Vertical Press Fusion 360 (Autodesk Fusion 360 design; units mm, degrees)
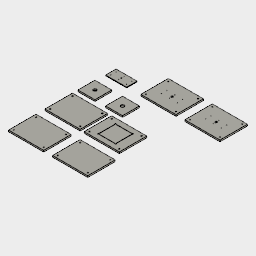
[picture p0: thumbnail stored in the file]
sketch "Top Metal"
  line L1 (240, 0) -> (0, 0)
  line L2 (240, 120) -> (240, 0)
  line L3 (0, 120) -> (240, 120)
  line L4 (0, 0) -> (0, 120)
  circle C1 centre (30, 90) radius 3.05
  circle C2 centre (30, 30) radius 3.05
  circle C3 centre (120, 90) radius 3.05
  circle C4 centre (120, 30) radius 3.05
  circle C5 centre (210, 30) radius 3.05
  circle C6 centre (210, 90) radius 3.05
  circle C7 centre (120, 60) radius 6
  point P2 (0, 0)
  point P3 (240, 0)
  point P5 (0, 120)
  point P6 (30, 90)
  point P8 (120, 90)
  point P11 (210, 90)
  point P10 (210, 30)
  point P9 (120, 30)
  point P7 (30, 30)
  point P12 (120, 60)
  dimension "d10" distance P2 P3 = 240
  dimension "d11" distance P2 P5 = 120
  dimension "d12" diameter C1 = 6.1
  dimension "d13" diameter C2 = 6.1
  dimension "d14" diameter C3 = 6.1
  dimension "d15" diameter C4 = 6.1
  dimension "d16" diameter C5 = 6.1
  dimension "d17" diameter C6 = 6.1
  dimension "d18" diameter C7 = 12
  dimension "d19" distance L4 P6 = 30
  dimension "d20" distance L4 P8 = 120
  dimension "d21" distance L2 P11 = 30
  dimension "d22" distance L2 P10 = 30
  dimension "d23" distance L4 P9 = 120
  dimension "d24" distance L4 P7 = 30
  dimension "d25" distance L4 P12 = 120
  dimension "d26" distance L3 P6 = 30
  dimension "d27" distance L3 P8 = 30
  dimension "d28" distance L3 P11 = 30
  dimension "d29" distance L1 P10 = 30
  dimension "d30" distance L1 P9 = 30
  dimension "d31" distance L1 P7 = 30
  dimension "d32" distance L1 P12 = 60
sketch "Sketch1"
  line L1 (800, 0) -> (400, 0)
  line L2 (800, 313) -> (800, 0)
  line L3 (400, 313) -> (800, 313)
  line L4 (400, 0) -> (400, 313)
  line L5 (610.8542, 156.5071) -> (605.4332, 147.1035)
  line L6 (605.4209, 165.9035) -> (610.8542, 156.5071)
  line L7 (594.5668, 165.8965) -> (605.4209, 165.9035)
  line L8 (589.1458, 156.4929) -> (594.5668, 165.8965)
  line L9 (594.5791, 147.0965) -> (589.1458, 156.4929)
  line L10 (605.4332, 147.1035) -> (594.5791, 147.0965)
  circle C1 centre (430, 30) radius 6
  circle C2 centre (430, 283) radius 6
  circle C3 centre (770, 283) radius 6
  circle C4 centre (770, 30) radius 6
  circle C5 centre (510, 186.5) radius 3.05
  circle C6 centre (600, 186.5) radius 3.05
  circle C7 centre (690, 186.5) radius 3.05
  circle C8 centre (690, 126.5) radius 3.05
  circle C9 centre (600, 126.5) radius 3.05
  circle C10 centre (510, 126.5) radius 3.05
  point P2 (400, 0)
  point P3 (800, 0)
  point P5 (400, 313)
  point P22 (600, 156.5)
  point P7 (430, 283)
  point P8 (770, 283)
  point P9 (770, 30)
  point P6 (430, 30)
  point P10 (510, 186.5)
  point P12 (690, 186.5)
  point P15 (510, 126.5)
  point P13 (690, 126.5)
  point P14 (600, 126.5)
  point P11 (600, 186.5)
  dimension "d33" distance P2 P3 = 400
  dimension "d34" distance P2 P5 = 313
  dimension "d35" diameter C1 = 12
  dimension "d36" diameter C2 = 12
  dimension "d37" diameter C3 = 12
  dimension "d38" diameter C4 = 12
  dimension "d39" diameter C5 = 6.1
  dimension "d40" diameter C6 = 6.1
  dimension "d41" diameter C7 = 6.1
  dimension "d42" diameter C8 = 6.1
  dimension "d43" diameter C9 = 6.1
  dimension "d44" diameter C10 = 6.1
  dimension "d45" distance L4 P22 = 200
  dimension "d46" distance L3 P22 = 156.5
  dimension "d47" distance L3 P7 = 30
  dimension "d48" distance L4 P7 = 30
  dimension "d49" distance L3 P8 = 30
  dimension "d50" distance L2 P8 = 30
  dimension "d51" distance L2 P9 = 30
  dimension "d52" distance L1 P9 = 30
  dimension "d53" distance L1 P6 = 30
  dimension "d54" distance L4 P6 = 30
  dimension "d55" distance L4 P10 = 110
  dimension "d56" distance L3 P10 = 126.5
  dimension "d57" distance L2 P12 = 110
  dimension "d58" distance L3 P12 = 126.5
  dimension "d59" distance L4 P15 = 110
  dimension "d60" distance L1 P15 = 126.5
  dimension "d61" distance L2 P13 = 110
  dimension "d62" distance L1 P13 = 126.5
  dimension "d63" distance L1 P14 = 126.5
  dimension "d64" distance L3 P11 = 126.5
  dimension "d65" distance L4 P11 = 200
  dimension "d66" distance L4 P14 = 200
  dimension "d194" distance L5 L8 = 18.8
sketch "Sketch1"
  line L1 (800, 0) -> (400, 0)
  line L2 (800, 313) -> (800, 0)
  line L3 (400, 313) -> (800, 313)
  line L4 (400, 0) -> (400, 313)
  line L5 (610.8542, 156.5061) -> (605.4324, 147.1031)
  line L6 (605.4218, 165.9031) -> (610.8542, 156.5061)
  line L7 (594.5676, 165.8969) -> (605.4218, 165.9031)
  line L8 (589.1458, 156.4939) -> (594.5676, 165.8969)
  line L9 (594.5782, 147.0969) -> (589.1458, 156.4939)
  line L10 (605.4324, 147.1031) -> (594.5782, 147.0969)
  circle C1 centre (430, 30) radius 6
  circle C2 centre (430, 283) radius 6
  circle C3 centre (770, 283) radius 6
  circle C4 centre (770, 30) radius 6
  circle C5 centre (510, 186.5) radius 3.05
  circle C6 centre (600, 186.5) radius 3.05
  circle C7 centre (690, 186.5) radius 3.05
  circle C8 centre (690, 126.5) radius 3.05
  circle C9 centre (600, 126.5) radius 3.05
  circle C10 centre (510, 126.5) radius 3.05
  point P2 (400, 0)
  point P3 (800, 0)
  point P5 (400, 313)
  point P22 (600, 156.5)
  point P7 (430, 283)
  point P8 (770, 283)
  point P9 (770, 30)
  point P6 (430, 30)
  point P10 (510, 186.5)
  point P12 (690, 186.5)
  point P15 (510, 126.5)
  point P13 (690, 126.5)
  point P14 (600, 126.5)
  point P11 (600, 186.5)
  dimension "d33_1" distance P2 P3 = 400
  dimension "d34_1" distance P2 P5 = 313
  dimension "d35_1" diameter C1 = 12
  dimension "d36_1" diameter C2 = 12
  dimension "d37_1" diameter C3 = 12
  dimension "d38_1" diameter C4 = 12
  dimension "d39_1" diameter C5 = 6.1
  dimension "d40_1" diameter C6 = 6.1
  dimension "d41_1" diameter C7 = 6.1
  dimension "d42_1" diameter C8 = 6.1
  dimension "d43_1" diameter C9 = 6.1
  dimension "d44_1" diameter C10 = 6.1
  dimension "d45_1" distance L4 P22 = 200
  dimension "d46_1" distance L3 P22 = 156.5
  dimension "d47_1" distance L3 P7 = 30
  dimension "d48_1" distance L4 P7 = 30
  dimension "d49_1" distance L3 P8 = 30
  dimension "d50_1" distance L2 P8 = 30
  dimension "d51_1" distance L2 P9 = 30
  dimension "d52_1" distance L1 P9 = 30
  dimension "d53_1" distance L1 P6 = 30
  dimension "d54_1" distance L4 P6 = 30
  dimension "d55_1" distance L4 P10 = 110
  dimension "d56_1" distance L3 P10 = 126.5
  dimension "d57_1" distance L2 P12 = 110
  dimension "d58_1" distance L3 P12 = 126.5
  dimension "d59_1" distance L4 P15 = 110
  dimension "d60_1" distance L1 P15 = 126.5
  dimension "d61_1" distance L2 P13 = 110
  dimension "d62_1" distance L1 P13 = 126.5
  dimension "d63_1" distance L1 P14 = 126.5
  dimension "d64_1" distance L3 P11 = 126.5
  dimension "d65_1" distance L4 P11 = 200
  dimension "d66_1" distance L4 P14 = 200
  dimension "d195" distance L5 L8 = 18.8
position "Position1"
sketch "Sketch1"
  line L1 (193, -120.8319) -> (0, -120.8319)
  line L2 (193, -313.8319) -> (193, -120.8319)
  line L3 (0, -313.8319) -> (193, -313.8319)
  line L4 (0, -120.8319) -> (0, -313.8319)
  circle C1 centre (96.5, -217.3319) radius 6
  point P2 (0, -120.8319)
  point P3 (193, -120.8319)
  point P5 (0, -313.8319)
  point P6 (96.5, -217.3319)
  dimension "d67" distance P2 P3 = 193
  dimension "d68" distance P2 P5 = 193
  dimension "d69" diameter C1 = 12
  dimension "d71" distance L1 P6 = 96.5
  dimension "d72" distance L4 P6 = 96.5
sketch "Sketch1"
  line L1 (507.061, -313.8319) -> (314.061, -313.8319)
  line L2 (507.061, -120.8319) -> (507.061, -313.8319)
  line L3 (314.061, -120.8319) -> (507.061, -120.8319)
  line L4 (314.061, -313.8319) -> (314.061, -120.8319)
  point P2 (314.061, -313.8319)
  point P3 (507.061, -313.8319)
  point P5 (314.061, -120.8319)
  dimension "d76" distance P2 P3 = 193
  dimension "d77" distance P2 P5 = 193
sketch "Sketch1"
  line L1 (400, -375) -> (0, -375)
  line L2 (400, -688) -> (400, -375)
  line L3 (0, -688) -> (400, -688)
  line L4 (0, -375) -> (0, -688)
  circle C1 centre (30, -405) radius 7.5
  circle C2 centre (370, -405) radius 7.5
  circle C3 centre (370, -658) radius 7.5
  circle C4 centre (30, -658) radius 7.5
  point P2 (0, -375)
  point P3 (400, -375)
  point P5 (0, -688)
  point P6 (30, -405)
  point P7 (370, -405)
  point P8 (370, -658)
  point P9 (30, -658)
  dimension "d81" distance P2 P3 = 400
  dimension "d82" distance P2 P5 = 313
  dimension "d83" diameter C1 = 15
  dimension "d84" diameter C2 = 15
  dimension "d85" diameter C3 = 15
  dimension "d86" diameter C4 = 15
  dimension "d87" distance L1 P6 = 30
  dimension "d88" distance L4 P6 = 30
  dimension "d89" distance L2 P7 = 30
  dimension "d90" distance L1 P7 = 30
  dimension "d91" distance L2 P8 = 30
  dimension "d92" distance L3 P8 = 30
  dimension "d93" distance L4 P9 = 30
  dimension "d94" distance L3 P9 = 30
sketch "Sketch1"
  line L1 (845, -688) -> (445, -688)
  line L2 (845, -375) -> (845, -688)
  line L3 (445, -375) -> (845, -375)
  line L4 (445, -688) -> (445, -375)
  circle C1 centre (475, -658) radius 7.5
  circle C2 centre (475, -405) radius 7.5
  circle C3 centre (815, -405) radius 7.5
  circle C4 centre (815, -658) radius 7.5
  point P2 (445, -688)
  point P3 (845, -688)
  point P5 (445, -375)
  point P7 (475, -405)
  point P8 (815, -405)
  point P9 (815, -658)
  point P6 (475, -658)
  dimension "d95" distance P2 P3 = 400
  dimension "d96" distance P2 P5 = 313
  dimension "d97" diameter C1 = 15
  dimension "d98" diameter C2 = 15
  dimension "d99" diameter C3 = 15
  dimension "d100" diameter C4 = 15
  dimension "d101" distance L3 P7 = 30
  dimension "d102" distance L4 P7 = 30
  dimension "d103" distance L3 P8 = 30
  dimension "d104" distance L2 P8 = 30
  dimension "d105" distance L2 P9 = 30
  dimension "d106" distance L1 P9 = 30
  dimension "d107" distance L1 P6 = 30
  dimension "d108" distance L4 P6 = 30
sketch "Sketch1"
  line L1 (400, -788.9071) -> (0, -788.9071)
  line L2 (400, -1101.9071) -> (400, -788.9071)
  line L3 (0, -1101.9071) -> (400, -1101.9071)
  line L4 (0, -788.9071) -> (0, -1101.9071)
  circle C1 centre (30, -818.9071) radius 6
  circle C2 centre (370, -818.9071) radius 6
  circle C3 centre (370, -1071.9071) radius 6
  circle C4 centre (30, -1071.9071) radius 6
  point P2 (0, -788.9071)
  point P3 (400, -788.9071)
  point P5 (0, -1101.9071)
  point P6 (30, -818.9071)
  point P7 (370, -818.9071)
  point P8 (370, -1071.9071)
  point P9 (30, -1071.9071)
  dimension "d118" distance P2 P3 = 400
  dimension "d119" distance P2 P5 = 313
  dimension "d120" diameter C1 = 12
  dimension "d121" diameter C2 = 12
  dimension "d122" diameter C3 = 12
  dimension "d123" diameter C4 = 12
  dimension "d124" distance L1 P6 = 30
  dimension "d125" distance L4 P6 = 30
  dimension "d126" distance L2 P7 = 30
  dimension "d127" distance L1 P7 = 30
  dimension "d128" distance L2 P8 = 30
  dimension "d129" distance L3 P8 = 30
  dimension "d130" distance L3 P9 = 30
  dimension "d131" distance L4 P9 = 30
sketch "Sketch1"
  line L1 (400, -788.9071) -> (0, -788.9071)
  line L2 (400, -1101.9071) -> (400, -788.9071)
  line L3 (0, -1101.9071) -> (400, -1101.9071)
  line L4 (0, -788.9071) -> (0, -1101.9071)
  circle C1 centre (30, -818.9071) radius 6
  circle C2 centre (370, -818.9071) radius 6
  circle C3 centre (370, -1071.9071) radius 6
  circle C4 centre (30, -1071.9071) radius 6
  point P2 (0, -788.9071)
  point P3 (400, -788.9071)
  point P5 (0, -1101.9071)
  point P6 (30, -818.9071)
  point P7 (370, -818.9071)
  point P8 (370, -1071.9071)
  point P9 (30, -1071.9071)
  dimension "d118_1" distance P2 P3 = 400
  dimension "d119_1" distance P2 P5 = 313
  dimension "d120_1" diameter C1 = 12
  dimension "d121_1" diameter C2 = 12
  dimension "d122_1" diameter C3 = 12
  dimension "d123_1" diameter C4 = 12
  dimension "d124_1" distance L1 P6 = 30
  dimension "d125_1" distance L4 P6 = 30
  dimension "d126_1" distance L2 P7 = 30
  dimension "d127_1" distance L1 P7 = 30
  dimension "d128_1" distance L2 P8 = 30
  dimension "d129_1" distance L3 P8 = 30
  dimension "d130_1" distance L3 P9 = 30
  dimension "d131_1" distance L4 P9 = 30
position "Position2"
extrude "Extrude1" sketch "Sketch1" blind 18 bodies "Base 2"
extrude "Extrude2" sketch "Sketch1" blind 18 bodies "Base 1"
extrude "Extrude3" sketch "Sketch1" blind 18 bodies "Plunger 3"
extrude "Extrude4" sketch "Sketch1" blind 18
sketch "Plunger 4 Recess" plane through (0, 0, 18) normal (0, 0, 1) x axis (-1, 0, 0)
  line L1 (-445, 688) -> (-445, 375)
  line L2 (-845, 688) -> (-445, 688)
  line L3 (-845, 375) -> (-845, 688)
  line L4 (-445, 375) -> (-845, 375)
  line L5 (-742, 434.5) -> (-548, 434.5)
  line L6 (-742, 628.5) -> (-742, 434.5)
  line L7 (-548, 628.5) -> (-742, 628.5)
  line L8 (-548, 434.5) -> (-548, 628.5)
  line L9 (-445, 688) -> (-445, 375)
  line L10 (-445, 375) -> (-845, 375)
  circle C1 centre (-475, 405) radius 7.5
  circle C2 centre (-815, 405) radius 7.5
  circle C3 centre (-475, 658) radius 7.5
  circle C4 centre (-815, 658) radius 7.5
  circle C5 centre (-548, 434.5) radius 6.05
  circle C6 centre (-742, 434.5) radius 6.05
  circle C7 centre (-742, 628.5) radius 6.05
  circle C8 centre (-548, 628.5) radius 6.05
  point P10 (-548, 434.5)
  point P11 (-742, 434.5)
  point P13 (-548, 628.5)
  point P14 (-548, 434.5)
  dimension "d165" distance P10 P11 = 194
  dimension "d166" distance P10 P13 = 194
  dimension "d167" diameter C5 = 12.1
  dimension "d168" diameter C6 = 12.1
  dimension "d169" diameter C7 = 12.1
  dimension "d170" diameter C8 = 12.1
  dimension "d171" distance P14 L9 = 103
  dimension "d172" distance P14 L10 = 59.5
extrude "Extrude5" sketch "Plunger 4 Recess" profile of L5 L6 L7 L8 C5 C6 C7 C8 blind -2
extrude "Extrude6" sketch "Sketch1" blind 18
sketch "Plunger 1 Recess" plane through (0, 0, 18) normal (0, 0, 1) x axis (-1, 0, 0)
  line L1 (-193, 313.8319) -> (0, 313.8319)
  line L2 (-193, 120.8319) -> (-193, 313.8319)
  line L3 (0, 120.8319) -> (-193, 120.8319)
  line L4 (0, 313.8319) -> (0, 120.8319)
  circle C1 centre (-96.5, 217.3319) radius 6
  circle C2 centre (-96.5, 217.3319) radius 17.75
  dimension "d177" diameter C2 = 35.5
extrude "Extrude7" sketch "Plunger 1 Recess" profile of C1 C2 blind -13.5
extrude "Extrude8" sketch "Sketch1" blind 18
sketch "Plunger 2 Recess" plane through (0, 0, 18) normal (0, 0, 1) x axis (-1, 0, 0)
  line L1 (-314.061, 313.8319) -> (-314.061, 120.8319)
  line L2 (-507.061, 313.8319) -> (-314.061, 313.8319)
  line L3 (-507.061, 120.8319) -> (-507.061, 313.8319)
  line L4 (-314.061, 120.8319) -> (-507.061, 120.8319)
  circle C1 centre (-410.561, 217.3319) radius 17.75
  point P6 (-410.561, 217.3319)
  dimension "d182" diameter C1 = 35.5
  dimension "d183" distance L1 P6 = 96.5
  dimension "d184" distance L4 P6 = 96.5
extrude "Extrude9" sketch "Plunger 2 Recess" profile of C1 blind -5.5
extrude "Extrude10" sketch "Sketch1" blind 18
extrude "Extrude11" sketch "Sketch1" blind 18
extrude "Extrude12" sketch "Top Metal" blind 8
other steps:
create_component "CreateComponent1"
create_component "CreateComponent3"
create_component "CreateComponent4"
create_component "CreateComponent1"
create_component "CreateComponent5"
create_component "CreateComponent8"
create_component "CreateComponent9"
create_component "CreateComponent10"
create_component "CreateComponent11"
create_component "CreateComponent12"
create_component "CreateComponent1"
named bodies: "Base 2", "Base 1", "Plunger 3"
